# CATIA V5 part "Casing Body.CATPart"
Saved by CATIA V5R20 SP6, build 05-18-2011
Part number: Casing Body
Bounding box of the stored display mesh (mm): x -21 to 0, y -24.5 to 30.5, z -25 to 47.5
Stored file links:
  E:\#01 CATIA Lecture Materials\#06 DMU\#06 DMU Page01 KIN EX06\Casing Body.CATPart
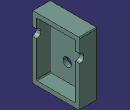
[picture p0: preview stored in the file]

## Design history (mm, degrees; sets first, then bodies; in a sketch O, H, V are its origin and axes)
Body1 (main body)
  Solid1: solid without history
